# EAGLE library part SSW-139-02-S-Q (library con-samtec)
THROUGH-HOLE .025" SQ POST SOCKET Source: Samtec SSW.pdf
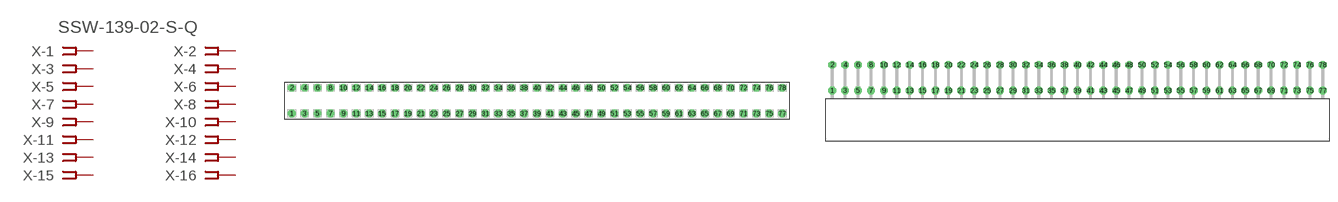
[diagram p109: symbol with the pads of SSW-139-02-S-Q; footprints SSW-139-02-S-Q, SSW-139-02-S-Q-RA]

Designator prefix X; gates -1=FPINV -2=FPIN -3=FPIN -4=FPIN -5=FPIN -6=FPIN -7=FPIN -8=FPIN -9=FPIN -10=FPIN -11=FPIN -12=FPIN -13=FPIN -14=FPIN -15=FPIN -16=FPIN -17=FPIN -18=FPIN -19=FPIN -20=FPIN -21=FPIN -22=FPIN -23=FPIN -24=FPIN -25=FPIN -26=FPIN -27=FPIN -28=FPIN -29=FPIN -30=FPIN -31=FPIN -32=FPIN -33=FPIN -34=FPIN -35=FPIN -36=FPIN -37=FPIN -38=FPIN -39=FPIN -40=FPIN -41=FPIN -42=FPIN -43=FPIN -44=FPIN -45=FPIN -46=FPIN -47=FPIN -48=FPIN -49=FPIN -50=FPIN -51=FPIN -52=FPIN -53=FPIN -54=FPIN -55=FPIN -56=FPIN -57=FPIN -58=FPIN -59=FPIN -60=FPIN -61=FPIN -62=FPIN -63=FPIN -64=FPIN -65=FPIN -66=FPIN -67=FPIN -68=FPIN -69=FPIN -70=FPIN -71=FPIN -72=FPIN -73=FPIN -74=FPIN -75=FPIN -76=FPIN -77=FPIN -78=FPIN

## SSW-139-02-S-Q (OC_FARNELL: unknown; OC_NEWARK: unknown)  [SSW-139-02-S-Q]
1  -1:1  pas
2  -2:1  pas
3  -3:1  pas
4  -4:1  pas
5  -5:1  pas
6  -6:1  pas
7  -7:1  pas
8  -8:1  pas
9  -9:1  pas
10  -10:1  pas
11  -11:1  pas
12  -12:1  pas
13  -13:1  pas
14  -14:1  pas
15  -15:1  pas
16  -16:1  pas
17  -17:1  pas
18  -18:1  pas
19  -19:1  pas
20  -20:1  pas
21  -21:1  pas
22  -22:1  pas
23  -23:1  pas
24  -24:1  pas
25  -25:1  pas
26  -26:1  pas
27  -27:1  pas
28  -28:1  pas
29  -29:1  pas
30  -30:1  pas
31  -31:1  pas
32  -32:1  pas
33  -33:1  pas
34  -34:1  pas
35  -35:1  pas
36  -36:1  pas
37  -37:1  pas
38  -38:1  pas
39  -39:1  pas
40  -40:1  pas
41  -41:1  pas
42  -42:1  pas
43  -43:1  pas
44  -44:1  pas
45  -45:1  pas
46  -46:1  pas
47  -47:1  pas
48  -48:1  pas
49  -49:1  pas
50  -50:1  pas
51  -51:1  pas
52  -52:1  pas
53  -53:1  pas
54  -54:1  pas
55  -55:1  pas
56  -56:1  pas
57  -57:1  pas
58  -58:1  pas
59  -59:1  pas
60  -60:1  pas
61  -61:1  pas
62  -62:1  pas
63  -63:1  pas
64  -64:1  pas
65  -65:1  pas
66  -66:1  pas
67  -67:1  pas
68  -68:1  pas
69  -69:1  pas
70  -70:1  pas
71  -71:1  pas
72  -72:1  pas
73  -73:1  pas
74  -74:1  pas
75  -75:1  pas
76  -76:1  pas
77  -77:1  pas
78  -78:1  pas

## SSW-139-02-S-QRA (OC_FARNELL: unknown; OC_NEWARK: unknown)  [SSW-139-02-S-Q-RA]
Pads as for SSW-139-02-S-Q

## Footprint SSW-139-02-S-Q (pad centres in mm)
THROUGH-HOLE .025" SQ POST SOCKET Source: Samtec SSW.pdf
drill 1 pad 1.5 octagon: 1 -48.26,-2.54; 2 -48.26,2.54; 3 -45.72,-2.54; 4 -45.72,2.54; 5 -43.18,-2.54; 6 -43.18,2.54; 7 -40.64,-2.54; 8 -40.64,2.54; 9 -38.1,-2.54; 10 -38.1,2.54; 11 -35.56,-2.54; 12 -35.56,2.54; 13 -33.02,-2.54; 14 -33.02,2.54; 15 -30.48,-2.54; 16 -30.48,2.54; 17 -27.94,-2.54; 18 -27.94,2.54; 19 -25.4,-2.54; 20 -25.4,2.54; 21 -22.86,-2.54; 22 -22.86,2.54; 23 -20.32,-2.54; 24 -20.32,2.54; 25 -17.78,-2.54; 26 -17.78,2.54; 27 -15.24,-2.54; 28 -15.24,2.54; 29 -12.7,-2.54; 30 -12.7,2.54; 31 -10.16,-2.54; 32 -10.16,2.54; 33 -7.62,-2.54; 34 -7.62,2.54; 35 -5.08,-2.54; 36 -5.08,2.54; 37 -2.54,-2.54; 38 -2.54,2.54; 39 0,-2.54; 40 0,2.54; 41 2.54,-2.54; 42 2.54,2.54; 43 5.08,-2.54; 44 5.08,2.54; 45 7.62,-2.54; 46 7.62,2.54; 47 10.16,-2.54; 48 10.16,2.54; 49 12.7,-2.54; 50 12.7,2.54; 51 15.24,-2.54; 52 15.24,2.54; 53 17.78,-2.54; 54 17.78,2.54; 55 20.32,-2.54; 56 20.32,2.54; 57 22.86,-2.54; 58 22.86,2.54; 59 25.4,-2.54; 60 25.4,2.54; 61 27.94,-2.54; 62 27.94,2.54; 63 30.48,-2.54; 64 30.48,2.54; 65 33.02,-2.54; 66 33.02,2.54; 67 35.56,-2.54; 68 35.56,2.54; 69 38.1,-2.54; 70 38.1,2.54; 71 40.64,-2.54; 72 40.64,2.54; 73 43.18,-2.54; 74 43.18,2.54; 75 45.72,-2.54; 76 45.72,2.54; 77 48.26,-2.54; 78 48.26,2.54

## Footprint SSW-139-02-S-Q-RA (pad centres in mm)
THROUGH-HOLE .025" SQ POST SOCKET Source: Samtec SSW.pdf
drill 1 pad 1.5 octagon: 1 -48.26,1.524; 2 -48.26,6.604; 3 -45.72,1.524; 4 -45.72,6.604; 5 -43.18,1.524; 6 -43.18,6.604; 7 -40.64,1.524; 8 -40.64,6.604; 9 -38.1,1.524; 10 -38.1,6.604; 11 -35.56,1.524; 12 -35.56,6.604; 13 -33.02,1.524; 14 -33.02,6.604; 15 -30.48,1.524; 16 -30.48,6.604; 17 -27.94,1.524; 18 -27.94,6.604; 19 -25.4,1.524; 20 -25.4,6.604; 21 -22.86,1.524; 22 -22.86,6.604; 23 -20.32,1.524; 24 -20.32,6.604; 25 -17.78,1.524; 26 -17.78,6.604; 27 -15.24,1.524; 28 -15.24,6.604; 29 -12.7,1.524; 30 -12.7,6.604; 31 -10.16,1.524; 32 -10.16,6.604; 33 -7.62,1.524; 34 -7.62,6.604; 35 -5.08,1.524; 36 -5.08,6.604; 37 -2.54,1.524; 38 -2.54,6.604; 39 0,1.524; 40 0,6.604; 41 2.54,1.524; 42 2.54,6.604; 43 5.08,1.524; 44 5.08,6.604; 45 7.62,1.524; 46 7.62,6.604; 47 10.16,1.524; 48 10.16,6.604; 49 12.7,1.524; 50 12.7,6.604; 51 15.24,1.524; 52 15.24,6.604; 53 17.78,1.524; 54 17.78,6.604; 55 20.32,1.524; 56 20.32,6.604; 57 22.86,1.524; 58 22.86,6.604; 59 25.4,1.524; 60 25.4,6.604; 61 27.94,1.524; 62 27.94,6.604; 63 30.48,1.524; 64 30.48,6.604; 65 33.02,1.524; 66 33.02,6.604; 67 35.56,1.524; 68 35.56,6.604; 69 38.1,1.524; 70 38.1,6.604; 71 40.64,1.524; 72 40.64,6.604; 73 43.18,1.524; 74 43.18,6.604; 75 45.72,1.524; 76 45.72,6.604; 77 48.26,1.524; 78 48.26,6.604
